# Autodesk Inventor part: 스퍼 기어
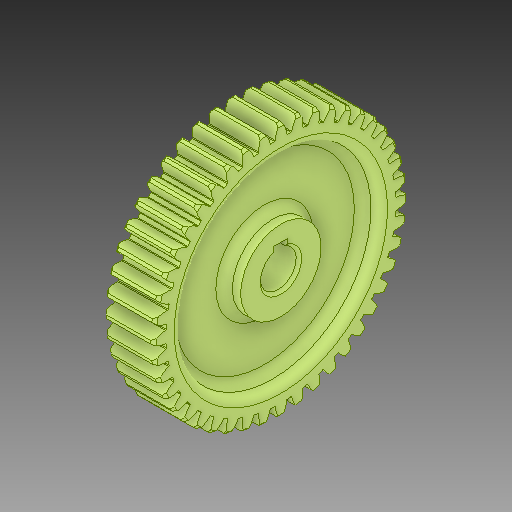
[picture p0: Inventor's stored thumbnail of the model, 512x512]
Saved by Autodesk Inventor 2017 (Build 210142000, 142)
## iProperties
Created: 2024-08
Part Number: 스퍼 기어
Material: 일반
Document SubType Name: Modeling
Designer: MRC
Density: 1 g/cm^3
Appearance: 기본값
Author: jhkim
Sending System: Autodesk Inventor 2025
Preprocessor: ST-DEVELOPER v20
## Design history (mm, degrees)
feature "솔리드1"
node "솔리드2"
